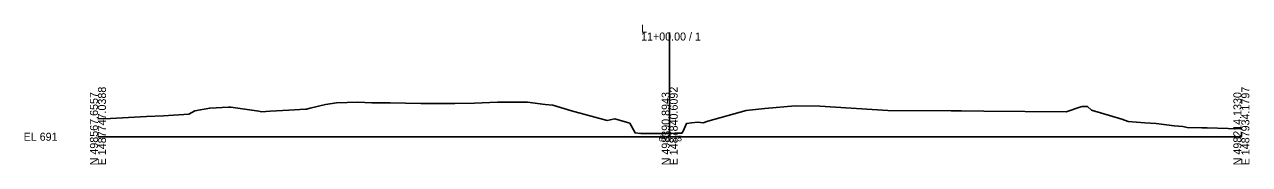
# Model space of a CAD drawing. Extents: x -26 to 4203, y -10 to 9538.
# Drawn here: x -25.7 to 402.8, y -9.7 to 39.2 of the extents above; entities that cross this region are included whole.
import ezdxf

# ---------------------------------------------------------------- set-up
doc = ezdxf.new("R2010")
doc.units = 0
for name, color, linetype in [('Default', 7, 'Continuous'), ('Exist Horizontal Alignment', 7, 'Continuous'), ('Prop Horizontal Alignment', 7, 'Continuous'), ('Scratch_Level_4', 7, 'Continuous')]:
    doc.layers.add(name, color=color, linetype=linetype)

msp = doc.modelspace()

# ---------------------------------------------------------------- linework, layer by layer
at = {"layer": 'Exist Horizontal Alignment'}
msp.add_lwpolyline([(0, 6.31), (4.4, 6.41), (17.03, 7.07), (22.94, 7.29), (31.76, 7.94), (33.87, 9.03), (39.09, 10.01), (45.64, 10.36), (46.49, 10.36), (56.26, 8.88), (57.2, 8.75), (60.3, 8.92), (66.76, 9.23), (72.57, 9.65), (72.97, 9.65), (74.26, 9.96), (79.59, 11.26), (83.49, 11.89), (90.91, 12.11), (95.86, 11.82), (102.27, 11.85), (112.9, 11.65), (114.14, 11.62), (124.9, 11.61), (131.74, 11.79), (139.75, 12.11), (144.03, 12.1), (150.22, 12.14), (156.45, 11.31), (159.08, 11.07), (165.63, 9.09), (178.11, 5.63), (179.21, 5.96), (180.83, 6.28), (185.28, 5.01), (186.03, 4.71), (187.89, 1.35), (189.89, 1.18), (190.5, 1.17), (199.12, 1.15), (200, 1.15), (200.75, 1.16), (201.76, 1.2), (204.27, 1.22), (204.74, 2), (205.86, 4.61), (207.69, 4.87), (209.91, 5.09), (211.69, 4.91), (213.35, 5.39), (226.78, 9.19), (233.29, 9.87), (243.85, 10.81), (252.5, 10.63), (276.34, 9.21), (298.43, 9.09), (302.14, 9.05), (309.92, 8.9), (338.76, 8.76), (343.86, 10.4), (344.27, 10.53), (346.12, 10.53), (347.62, 9.24), (358.19, 6.17), (360.36, 5.36), (366.25, 4.82), (370.16, 4.6), (376.54, 3.76), (379.47, 3.55), (380.98, 3.25), (386.17, 3.08), (387.98, 3.08), (395.43, 2.91), (400, 2.76)], dxfattribs=at)
at = {"layer": 'Scratch_Level_4'}
for p, q in [((200, 0), (200, 36.42)), ((0, 0), (200, 0)), ((200, 0), (400, 0))]:
    msp.add_line(p, q, dxfattribs=at)

# ---------------------------------------------------------------- texts
at = {"layer": 'Default'}
msp.add_text('-', height=0.0001, dxfattribs=at).set_placement((0, 0))
at = {"layer": 'Prop Horizontal Alignment'}
msp.add_text('692.15', height=2, dxfattribs=at).set_placement((196.1, -1.6))
at = {"layer": 'Scratch_Level_4'}
for s, p in [('L', (190, 36.42)), ('11+00.00 / 1', (190, 33.62)), ('EL 691', (-26, -1.4))]:
    msp.add_text(s, height=2.8, dxfattribs=at).set_placement(p)
for s, p in [('E 1487747.0388', (2.8, -10)), ('E 1487840.6092', (202.8, -10)), ('E 1487934.1797', (402.8, -10)), ('N 498567.6557', (0, -10)), ('N 498390.8943', (200, -10)), ('N 498214.1330', (400, -10))]:
    msp.add_text(s, height=2.8, rotation=90, dxfattribs=at).set_placement(p)

doc.saveas('drawing.dxf')
